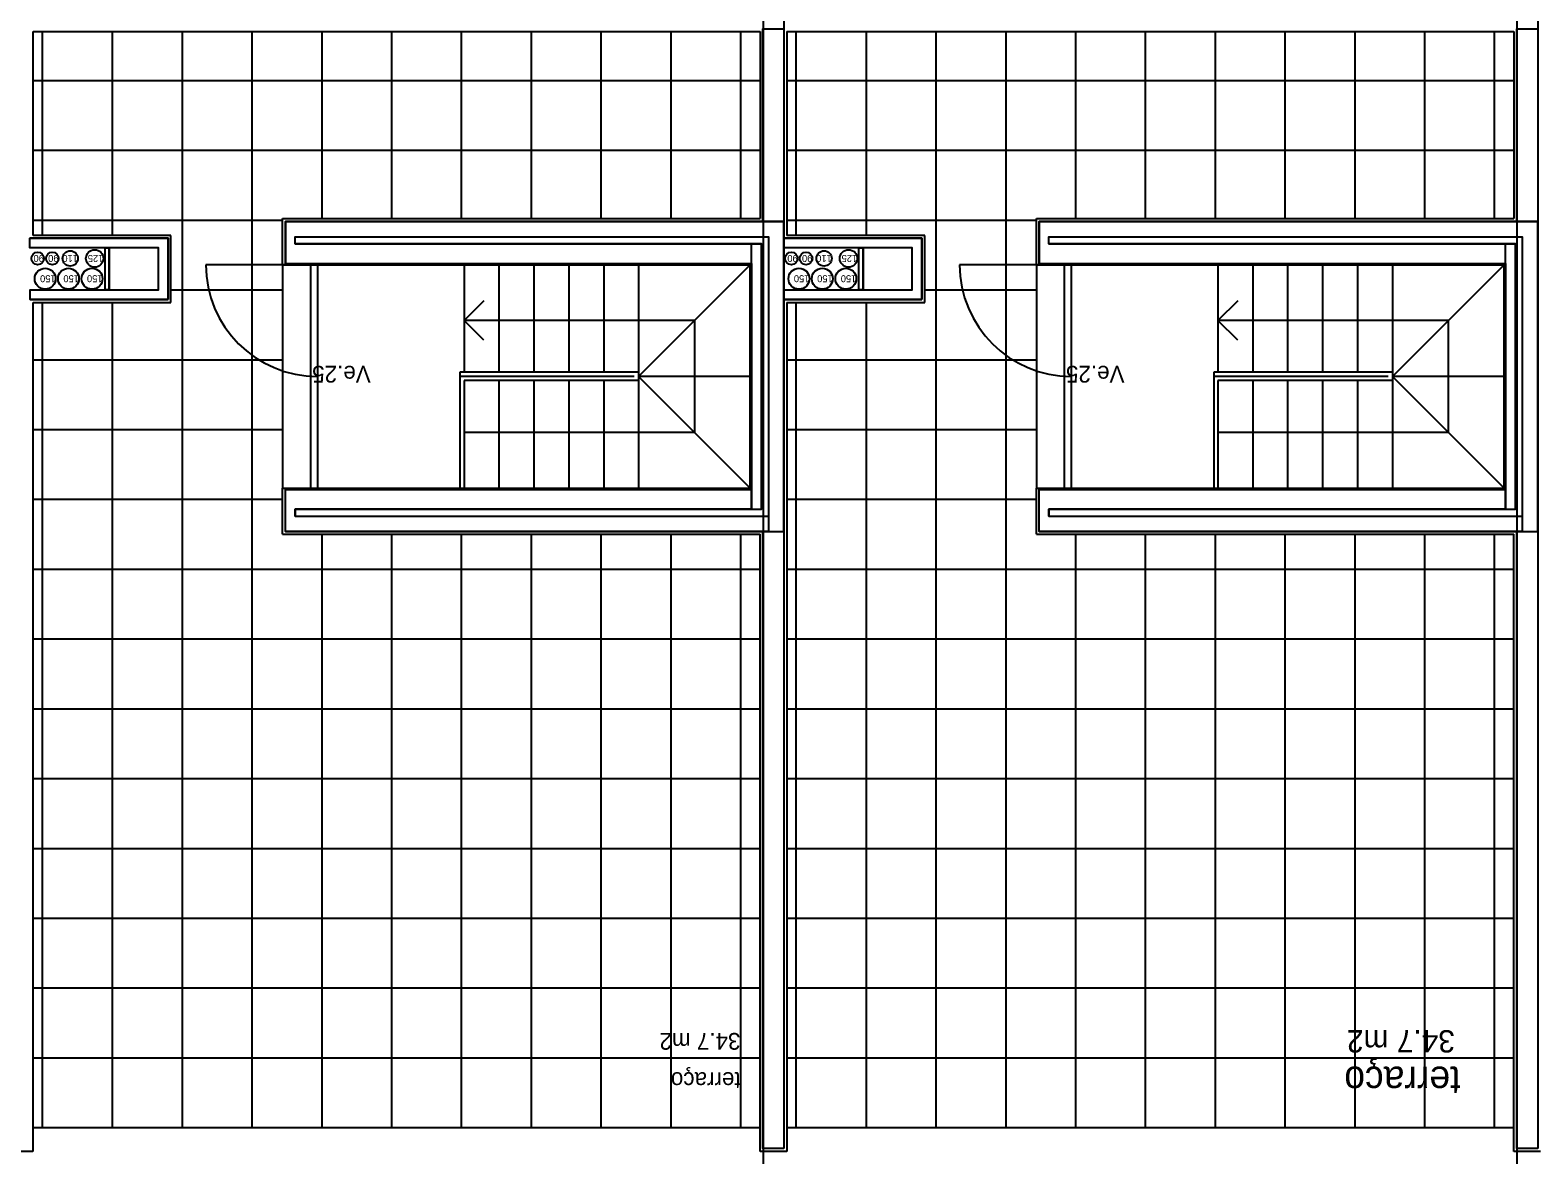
# Model space of a CAD drawing. Extents: x 1278 to 1356, y -253.7 to -224.
# Drawn here: x 1334.83 to 1345.63, y -246.8 to -238.74 of the extents above; entities that cross this region are included whole.
import ezdxf

# ---------------------------------------------------------------- set-up
doc = ezdxf.new("R2010")
doc.units = 0
for name, color, linetype in [('corte', 7, 'Continuous'), ('estereoctomias', 7, 'Continuous'), ('estrutura-eixos', 7, 'Continuous'), ('Level 1', 7, 'Continuous'), ('Level 13', 7, 'Continuous'), ('Level 2', 7, 'Continuous'), ('Level 21', 7, 'Continuous'), ('Level 40', 7, 'Continuous'), ('Level 41', 7, 'Continuous'), ('Level 60', 7, 'Continuous'), ('revestimentos', 7, 'Continuous')]:
    doc.layers.add(name, color=color, linetype=linetype)

msp = doc.modelspace()

# ---------------------------------------------------------------- linework, layer by layer
at = {"layer": 'corte'}
for p, q in [((1335.75, -240.304), (1334.83, -240.304)), ((1335.82, -240.234), (1334.832, -240.234)), ((1335.368, -240.604), (1335.368, -240.304)), ((1335.398, -240.604), (1335.398, -240.304)), ((1335.748, -240.304), (1335.748, -240.604)), ((1335.818, -240.234), (1335.818, -240.674)), ((1336.73, -240.224), (1340.121, -240.224)), ((1336.73, -240.274), (1336.73, -240.224)), ((1336.73, -240.274), (1340.071, -240.274)), ((1340.071, -240.274), (1340.071, -242.174)), ((1340.121, -240.224), (1340.121, -242.224)), ((1341.15, -240.304), (1340.23, -240.304)), ((1341.22, -240.234), (1340.232, -240.234)), ((1340.768, -240.604), (1340.768, -240.304)), ((1340.798, -240.604), (1340.798, -240.304)), ((1341.148, -240.304), (1341.148, -240.604)), ((1341.218, -240.234), (1341.218, -240.674)), ((1342.13, -240.224), (1345.521, -240.224)), ((1342.13, -240.274), (1342.13, -240.224)), ((1342.13, -240.274), (1345.471, -240.274)), ((1345.471, -240.274), (1345.471, -242.174)), ((1345.521, -240.224), (1345.521, -242.224)), ((1334.83, -240.604), (1335.75, -240.604)), ((1340.23, -240.604), (1341.15, -240.604)), ((1334.832, -240.674), (1335.82, -240.674)), ((1340.232, -240.674), (1341.22, -240.674))]:
    msp.add_line(p, q, dxfattribs=at)
at = {"layer": 'estereoctomias'}
for p, q in [((1334.92, -240.214), (1334.92, -238.754)), ((1340.32, -240.214), (1340.32, -238.754)), ((1334.92, -246.604), (1334.92, -240.694)), ((1340.32, -246.604), (1340.32, -240.694))]:
    msp.add_line(p, q, dxfattribs=at)
for points in [[(1340.231, -240.114), (1340.081, -240.114), (1340.081, -238.734), (1340.231, -238.734)], [(1345.631, -240.114), (1345.481, -240.114), (1345.481, -238.734), (1345.631, -238.734)], [(1340.231, -240.114), (1336.66, -240.114), (1336.66, -240.414), (1340, -240.414), (1340, -242.174), (1340.071, -242.174), (1340.071, -240.414), (1340.071, -240.284), (1340.071, -240.274), (1336.73, -240.274), (1336.73, -240.224), (1340.121, -240.224), (1340.121, -242.334), (1340.231, -242.334), (1340.231, -240.224)], [(1345.631, -240.114), (1342.06, -240.114), (1342.06, -240.414), (1345.4, -240.414), (1345.4, -242.174), (1345.471, -242.174), (1345.471, -240.414), (1345.471, -240.284), (1345.471, -240.274), (1342.13, -240.274), (1342.13, -240.224), (1345.521, -240.224), (1345.521, -242.334), (1345.631, -242.334), (1345.631, -240.224)], [(1335.82, -240.674), (1334.832, -240.674), (1334.832, -240.604), (1335.75, -240.604), (1335.75, -240.304), (1334.83, -240.304), (1334.83, -240.234), (1335.82, -240.234)], [(1335.398, -240.604), (1335.368, -240.604), (1335.368, -240.304), (1335.398, -240.304)], [(1341.22, -240.674), (1340.232, -240.674), (1340.232, -240.604), (1341.15, -240.604), (1341.15, -240.304), (1340.23, -240.304), (1340.23, -240.234), (1341.22, -240.234)], [(1340.798, -240.604), (1340.768, -240.604), (1340.768, -240.304), (1340.798, -240.304)], [(1340.121, -242.224), (1340.121, -242.334), (1336.66, -242.334), (1336.66, -242.034), (1340, -242.034), (1340, -242.174), (1336.73, -242.174), (1336.73, -242.224)], [(1345.521, -242.224), (1345.521, -242.334), (1342.06, -242.334), (1342.06, -242.034), (1345.4, -242.034), (1345.4, -242.174), (1342.13, -242.174), (1342.13, -242.224)], [(1340.231, -246.754), (1340.081, -246.754), (1340.081, -242.334), (1340.231, -242.334)], [(1345.631, -246.754), (1345.481, -246.754), (1345.481, -242.334), (1345.631, -242.334)]]:
    msp.add_lwpolyline(points, close=True, dxfattribs=at)
at = {"layer": 'estrutura-eixos'}
for p, q in [((1340.084, -250.792), (1340.084, -229.62)), ((1345.484, -250.792), (1345.484, -229.62))]:
    msp.add_line(p, q, dxfattribs=at)
at = {"layer": 'Level 1'}
for p, q in [((1340.231, -232.094), (1340.231, -246.754)), ((1345.631, -232.094), (1345.631, -246.754)), ((1340.081, -240.114), (1340.081, -238.734)), ((1345.481, -240.114), (1345.481, -238.734)), ((1336.66, -240.114), (1340.231, -240.114)), ((1336.66, -240.414), (1336.66, -240.114)), ((1342.06, -240.114), (1345.631, -240.114)), ((1342.06, -240.414), (1342.06, -240.114)), ((1340, -242.174), (1340, -240.274)), ((1345.4, -242.174), (1345.4, -240.274)), ((1336.66, -240.414), (1340, -240.414)), ((1342.06, -240.414), (1345.4, -240.414)), ((1336.66, -242.034), (1340, -242.034)), ((1336.66, -242.334), (1336.66, -242.034)), ((1342.06, -242.034), (1345.4, -242.034)), ((1342.06, -242.334), (1342.06, -242.034)), ((1336.73, -242.174), (1340.071, -242.174)), ((1336.73, -242.224), (1336.73, -242.174)), ((1336.73, -242.224), (1340.121, -242.224)), ((1342.13, -242.174), (1345.471, -242.174)), ((1342.13, -242.224), (1342.13, -242.174)), ((1342.13, -242.224), (1345.521, -242.224)), ((1336.66, -242.334), (1340.231, -242.334)), ((1340.081, -246.754), (1340.081, -242.334)), ((1342.06, -242.334), (1345.631, -242.334)), ((1345.481, -246.754), (1345.481, -242.334)), ((1340.231, -246.754), (1340.081, -246.754)), ((1345.631, -246.754), (1345.481, -246.754))]:
    msp.add_line(p, q, dxfattribs=at)
at = {"layer": 'Level 13'}
for p, q in [((1336.84, -240.424), (1336.09, -240.424)), ((1336.84, -240.424), (1336.84, -242.024)), ((1336.89, -240.424), (1336.89, -242.024)), ((1342.24, -240.424), (1341.49, -240.424)), ((1342.24, -240.424), (1342.24, -242.024)), ((1342.29, -240.424), (1342.29, -242.024))]:
    msp.add_line(p, q, dxfattribs=at)
for centre in [(1336.89, -240.424), (1342.29, -240.424)]:
    msp.add_arc(centre, 0.8, 180, 270, dxfattribs=at)
at = {"layer": 'Level 2'}
for p, q in [((1336.64, -240.424), (1336.64, -242.024)), ((1337.94, -240.424), (1337.94, -241.194)), ((1338.19, -240.424), (1338.19, -241.194)), ((1338.44, -240.424), (1338.44, -241.194)), ((1338.69, -240.424), (1338.69, -241.194)), ((1338.94, -240.424), (1338.94, -241.194)), ((1339.19, -240.424), (1339.19, -241.194)), ((1339.19, -241.224), (1339.99, -240.424)), ((1342.04, -240.424), (1342.04, -242.024)), ((1343.34, -240.424), (1343.34, -241.194)), ((1343.59, -240.424), (1343.59, -241.194)), ((1343.84, -240.424), (1343.84, -241.194)), ((1344.09, -240.424), (1344.09, -241.194)), ((1344.34, -240.424), (1344.34, -241.194)), ((1344.59, -240.424), (1344.59, -241.194)), ((1344.59, -241.224), (1345.39, -240.424)), ((1338.082, -240.683), (1337.94, -240.824)), ((1343.482, -240.683), (1343.34, -240.824)), ((1339.59, -240.824), (1337.94, -240.824)), ((1338.082, -240.965), (1337.94, -240.824)), ((1339.59, -240.824), (1339.59, -241.624)), ((1344.99, -240.824), (1343.34, -240.824)), ((1343.482, -240.965), (1343.34, -240.824)), ((1344.99, -240.824), (1344.99, -241.624)), ((1339.19, -241.194), (1337.91, -241.194)), ((1337.91, -241.194), (1337.91, -242.024)), ((1339.159, -241.224), (1337.91, -241.224)), ((1339.19, -241.254), (1337.94, -241.254)), ((1337.94, -241.254), (1337.94, -242.024)), ((1337.94, -241.254), (1337.94, -242.024)), ((1338.19, -241.254), (1338.19, -242.024)), ((1338.44, -241.254), (1338.44, -242.024)), ((1338.69, -241.254), (1338.69, -242.024)), ((1338.94, -241.254), (1338.94, -242.024)), ((1339.19, -241.194), (1339.19, -241.254)), ((1339.99, -241.224), (1339.19, -241.224)), ((1339.19, -241.224), (1339.99, -242.024)), ((1339.19, -241.254), (1339.19, -242.024)), ((1344.59, -241.194), (1343.31, -241.194)), ((1343.31, -241.194), (1343.31, -242.024)), ((1344.559, -241.224), (1343.31, -241.224)), ((1344.59, -241.254), (1343.34, -241.254)), ((1343.34, -241.254), (1343.34, -242.024)), ((1343.34, -241.254), (1343.34, -242.024)), ((1343.59, -241.254), (1343.59, -242.024)), ((1343.84, -241.254), (1343.84, -242.024)), ((1344.09, -241.254), (1344.09, -242.024)), ((1344.34, -241.254), (1344.34, -242.024)), ((1344.59, -241.194), (1344.59, -241.254)), ((1345.39, -241.224), (1344.59, -241.224)), ((1344.59, -241.224), (1345.39, -242.024)), ((1344.59, -241.254), (1344.59, -242.024)), ((1337.94, -241.624), (1339.59, -241.624)), ((1343.34, -241.624), (1344.99, -241.624)), ((1334.852, -246.604), (1340.061, -246.604)), ((1340.252, -246.604), (1345.461, -246.604))]:
    msp.add_line(p, q, dxfattribs=at)
at = {"layer": 'Level 21'}
for p, q in [((1335.42, -238.754), (1335.42, -240.214)), ((1335.92, -238.754), (1335.92, -246.604)), ((1336.42, -238.754), (1336.42, -246.604)), ((1336.92, -238.754), (1336.92, -240.094)), ((1337.42, -238.754), (1337.42, -240.094)), ((1337.92, -238.754), (1337.92, -240.094)), ((1338.42, -238.754), (1338.42, -240.094)), ((1338.92, -238.754), (1338.92, -240.094)), ((1339.42, -238.754), (1339.42, -240.094)), ((1339.92, -238.754), (1339.92, -240.094)), ((1340.82, -238.754), (1340.82, -240.214)), ((1341.32, -238.754), (1341.32, -246.604)), ((1341.82, -238.754), (1341.82, -246.604)), ((1342.32, -238.754), (1342.32, -240.094)), ((1342.82, -238.754), (1342.82, -240.094)), ((1343.32, -238.754), (1343.32, -240.094)), ((1343.82, -238.754), (1343.82, -240.094)), ((1344.32, -238.754), (1344.32, -240.094)), ((1344.82, -238.754), (1344.82, -240.094)), ((1345.32, -238.754), (1345.32, -240.094)), ((1334.852, -239.104), (1340.061, -239.104)), ((1340.252, -239.104), (1345.461, -239.104)), ((1334.852, -239.604), (1340.061, -239.604)), ((1340.252, -239.604), (1345.461, -239.604)), ((1334.852, -240.104), (1336.64, -240.104)), ((1340.252, -240.104), (1342.04, -240.104)), ((1335.838, -240.604), (1336.64, -240.604)), ((1341.238, -240.604), (1342.04, -240.604)), ((1335.42, -240.694), (1335.42, -246.604)), ((1340.82, -240.694), (1340.82, -246.604)), ((1334.852, -241.104), (1336.64, -241.104)), ((1340.252, -241.104), (1342.04, -241.104)), ((1334.852, -241.604), (1336.64, -241.604)), ((1340.252, -241.604), (1342.04, -241.604)), ((1334.852, -242.104), (1336.64, -242.104)), ((1340.252, -242.104), (1342.04, -242.104)), ((1336.92, -242.354), (1336.92, -246.604)), ((1337.42, -242.354), (1337.42, -246.604)), ((1337.92, -242.354), (1337.92, -246.604)), ((1338.42, -242.354), (1338.42, -246.604)), ((1338.92, -242.354), (1338.92, -246.604)), ((1339.42, -242.354), (1339.42, -246.604)), ((1339.92, -242.354), (1339.92, -246.604)), ((1342.32, -242.354), (1342.32, -246.604)), ((1342.82, -242.354), (1342.82, -246.604)), ((1343.32, -242.354), (1343.32, -246.604)), ((1343.82, -242.354), (1343.82, -246.604)), ((1344.32, -242.354), (1344.32, -246.604)), ((1344.82, -242.354), (1344.82, -246.604)), ((1345.32, -242.354), (1345.32, -246.604)), ((1334.852, -242.604), (1340.061, -242.604)), ((1340.252, -242.604), (1345.461, -242.604)), ((1334.852, -243.104), (1340.061, -243.104)), ((1340.252, -243.104), (1345.461, -243.104)), ((1334.852, -243.604), (1340.061, -243.604)), ((1340.252, -243.604), (1345.461, -243.604)), ((1334.852, -244.104), (1340.061, -244.104)), ((1340.252, -244.104), (1345.461, -244.104)), ((1334.852, -244.604), (1340.061, -244.604)), ((1340.252, -244.604), (1345.461, -244.604)), ((1334.852, -245.104), (1340.061, -245.104)), ((1340.252, -245.104), (1345.461, -245.104)), ((1334.852, -245.604), (1340.061, -245.604)), ((1340.252, -245.604), (1345.461, -245.604)), ((1334.852, -246.104), (1340.061, -246.104)), ((1340.252, -246.104), (1345.461, -246.104))]:
    msp.add_line(p, q, dxfattribs=at)
at = {"layer": 'Level 41'}
for centre, radius in [((1335.294, -240.379), 0.0625), ((1340.694, -240.379), 0.0625), ((1334.885, -240.379), 0.045), ((1334.99, -240.379), 0.045), ((1335.119, -240.379), 0.055), ((1340.285, -240.379), 0.045), ((1340.39, -240.379), 0.045), ((1340.519, -240.379), 0.055), ((1334.939, -240.524), 0.075), ((1335.106, -240.524), 0.075), ((1335.275, -240.524), 0.075), ((1340.339, -240.524), 0.075), ((1340.506, -240.524), 0.075), ((1340.675, -240.524), 0.075)]:
    msp.add_circle(centre, radius, dxfattribs=at)
at = {"layer": 'revestimentos'}
for p, q in [((1334.851, -238.754), (1334.851, -240.214)), ((1334.852, -238.754), (1340.061, -238.754)), ((1340.061, -238.754), (1340.061, -240.094)), ((1340.251, -238.754), (1340.251, -240.214)), ((1340.252, -238.754), (1345.461, -238.754)), ((1345.461, -238.754), (1345.461, -240.094)), ((1336.64, -240.424), (1336.64, -240.094)), ((1336.64, -240.094), (1340.061, -240.094)), ((1342.04, -240.424), (1342.04, -240.094)), ((1342.04, -240.094), (1345.461, -240.094)), ((1335.84, -240.214), (1334.852, -240.214)), ((1335.838, -240.214), (1335.838, -240.694)), ((1341.24, -240.214), (1340.252, -240.214)), ((1341.238, -240.214), (1341.238, -240.694)), ((1336.64, -240.424), (1339.99, -240.424)), ((1339.99, -242.024), (1339.99, -240.424)), ((1342.04, -240.424), (1345.39, -240.424)), ((1345.39, -242.024), (1345.39, -240.424)), ((1334.851, -240.694), (1334.851, -246.774)), ((1334.852, -240.694), (1335.84, -240.694)), ((1340.251, -240.694), (1340.251, -246.774)), ((1340.252, -240.694), (1341.24, -240.694)), ((1336.64, -242.354), (1336.64, -242.024)), ((1336.64, -242.024), (1339.99, -242.024)), ((1342.04, -242.354), (1342.04, -242.024)), ((1342.04, -242.024), (1345.39, -242.024)), ((1336.64, -242.354), (1340.061, -242.354)), ((1340.061, -246.774), (1340.061, -242.354)), ((1342.04, -242.354), (1345.461, -242.354)), ((1345.461, -246.774), (1345.461, -242.354)), ((1334.851, -246.774), (1334.661, -246.774)), ((1340.251, -246.774), (1340.061, -246.774)), ((1345.651, -246.774), (1345.461, -246.774))]:
    msp.add_line(p, q, dxfattribs=at)

# ---------------------------------------------------------------- texts
at = {"layer": 'Level 40'}
for p in [(1337.271, -241.148), (1342.671, -241.148)]:
    msp.add_text('Ve.25', height=0.12, rotation=180, dxfattribs=at).set_placement(p)
at = {"layer": 'Level 41'}
for s, p in [('90', (1334.93, -240.354)), ('90', (1335.035, -240.354)), ('110', (1335.174, -240.354)), ('125', (1335.356, -240.354)), ('90', (1340.33, -240.354)), ('90', (1340.435, -240.354)), ('110', (1340.574, -240.354)), ('125', (1340.756, -240.354)), ('150', (1335.014, -240.499)), ('150', (1335.181, -240.499)), ('150', (1335.35, -240.499)), ('150', (1340.414, -240.499)), ('150', (1340.581, -240.499)), ('150', (1340.75, -240.499))]:
    msp.add_text(s, height=0.05, rotation=180, dxfattribs=at).set_placement(p)
at = {"layer": 'Level 60'}
for s, height, p in [('34.7 m2', 0.12, (1339.92, -245.926)), ('34.7 m2', 0.16, (1345.038, -245.906)), ('terraço', 0.2, (1345.078, -246.167)), ('terraço', 0.12, (1339.921, -246.207))]:
    msp.add_text(s, height=height, rotation=180, dxfattribs=at).set_placement(p)

doc.saveas('drawing.dxf')
